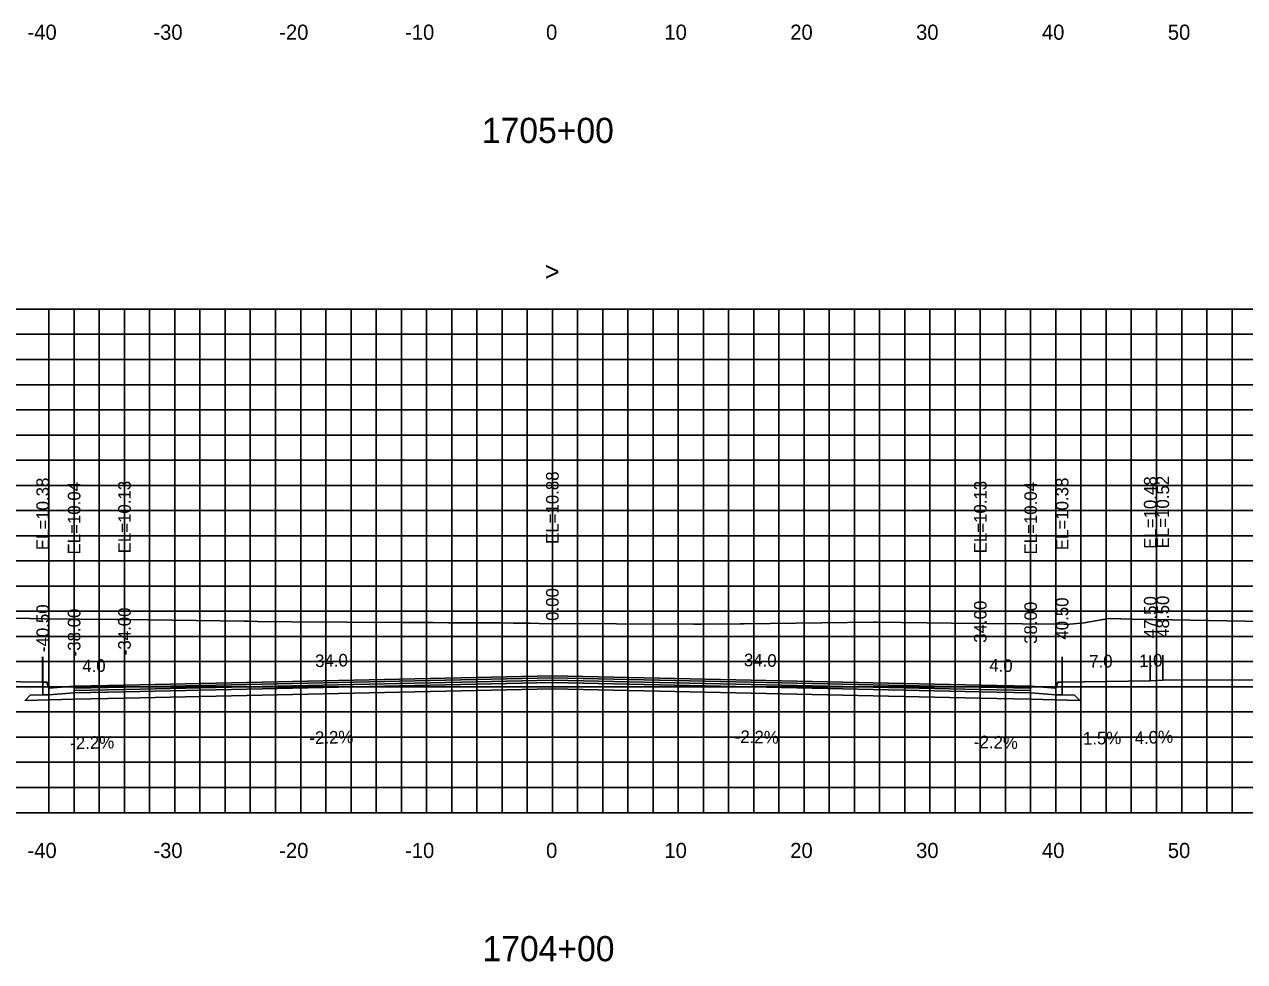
# Model space of a CAD drawing. Extents: x 1797789 to 1803805, y 249066 to 250293.
# Drawn here: x 1802929.1 to 1803026, y 250087.6 to 250162 of the extents above; entities that cross this region are included whole.
import ezdxf

# ---------------------------------------------------------------- set-up
doc = ezdxf.new("R2010")
doc.units = 0
for name, color, linetype in [('1', 7, 'Continuous'), ('10', 7, 'Continuous'), ('3', 7, 'Continuous'), ('4', 7, 'Continuous'), ('60', 7, 'Continuous'), ('BASE', 7, 'Continuous'), ('CL-CNST', 7, 'Continuous'), ('Level 62', 7, 'Continuous'), ('LOWER BINDER', 7, 'Continuous'), ('M-ROADS', 7, 'Continuous'), ('UPPER BINDER', 7, 'Continuous'), ('WEARING', 7, 'Continuous')]:
    doc.layers.add(name, color=color, linetype=linetype)

msp = doc.modelspace()

# ---------------------------------------------------------------- linework, layer by layer
for p, q in [((1802971.002, 250110.307), (1802971.002, 250112.307)), ((1802930.502, 250109.811), (1802930.502, 250111.811)), ((1802930.505, 250109.811), (1802930.505, 250111.811)), ((1802933.002, 250109.471), (1802933.002, 250111.471)), ((1802937.002, 250109.559), (1802937.002, 250111.559)), ((1803005.002, 250109.559), (1803005.002, 250111.559)), ((1803009.002, 250109.471), (1803009.002, 250111.471)), ((1803011.498, 250109.811), (1803011.498, 250111.811)), ((1803011.502, 250109.811), (1803011.502, 250111.811)), ((1803018.502, 250109.916), (1803018.502, 250111.916)), ((1803019.502, 250109.956), (1803019.502, 250111.956))]:
    msp.add_line(p, q)
for points in [[(1802933.002, 250109.471), (1802931.002, 250109.311), (1802930.835, 250109.811), (1802930.505, 250109.811), (1802930.505, 250108.781), (1802931.002, 250108.781), (1802933.002, 250108.941)], [(1803009.002, 250109.471), (1803011.002, 250109.311), (1803011.168, 250109.811), (1803011.498, 250109.811), (1803011.498, 250108.781), (1803011.002, 250108.781), (1803009.002, 250108.941)]]:
    msp.add_lwpolyline(points, close=True)
at = {"layer": '60'}
for p, q in [((1802821.002, 250099.432), (1803121.002, 250099.432)), ((1802931.002, 250099.372), (1802931.002, 250099.432)), ((1802941.002, 250099.372), (1802941.002, 250099.432)), ((1802951.002, 250099.372), (1802951.002, 250099.432)), ((1802961.002, 250099.372), (1802961.002, 250099.432)), ((1802971.002, 250099.372), (1802971.002, 250099.432)), ((1802981.002, 250099.372), (1802981.002, 250099.432)), ((1802991.002, 250099.372), (1802991.002, 250099.432)), ((1803001.002, 250099.372), (1803001.002, 250099.432)), ((1803011.002, 250099.372), (1803011.002, 250099.432)), ((1803021.002, 250099.372), (1803021.002, 250099.432))]:
    msp.add_line(p, q, dxfattribs=at)
at = {"layer": 'BASE'}
msp.add_lwpolyline([(1803009.002, 250108.441), (1803012.902, 250108.355), (1803012.498, 250108.759), (1803011.498, 250108.781), (1803011.002, 250108.781), (1803009.002, 250108.941), (1803005.002, 250109.029), (1802971.002, 250109.777), (1802937.002, 250109.029), (1802933.002, 250108.941), (1802931.002, 250108.781), (1802930.505, 250108.781), (1802929.505, 250108.759), (1802929.101, 250108.355), (1802933.002, 250108.441), (1802937.002, 250108.529), (1802971.002, 250109.277), (1803005.002, 250108.529)], close=True, dxfattribs=at)
at = {"layer": 'CL-CNST'}
msp.add_lwpolyline([(1802821.002, 250113.383), (1802922.502, 250109.956), (1802923.502, 250109.916), (1802930.502, 250109.811), (1802930.505, 250109.811), (1802930.835, 250109.811), (1802931.002, 250109.311), (1802933.002, 250109.471), (1802937.002, 250109.559), (1802971.002, 250110.307), (1803005.002, 250109.559), (1803009.002, 250109.471), (1803011.002, 250109.311), (1803011.168, 250109.811), (1803011.498, 250109.811), (1803011.502, 250109.811), (1803018.502, 250109.916), (1803019.502, 250109.956), (1803121.002, 250110.247)], dxfattribs=at)
at = {"layer": 'Level 62'}
for p, q in [((1802821.002, 250139.432), (1803121.002, 250139.432)), ((1802931.002, 250099.432), (1802931.002, 250139.432)), ((1802933.002, 250099.432), (1802933.002, 250139.432)), ((1802935.002, 250099.432), (1802935.002, 250139.432)), ((1802937.002, 250099.432), (1802937.002, 250139.432)), ((1802939.002, 250099.432), (1802939.002, 250139.432)), ((1802941.002, 250099.432), (1802941.002, 250139.432)), ((1802943.002, 250099.432), (1802943.002, 250139.432)), ((1802945.002, 250099.432), (1802945.002, 250139.432)), ((1802947.002, 250099.432), (1802947.002, 250139.432)), ((1802949.002, 250099.432), (1802949.002, 250139.432)), ((1802951.002, 250099.432), (1802951.002, 250139.432)), ((1802953.002, 250099.432), (1802953.002, 250139.432)), ((1802955.002, 250099.432), (1802955.002, 250139.432)), ((1802957.002, 250099.432), (1802957.002, 250139.432)), ((1802959.002, 250099.432), (1802959.002, 250139.432)), ((1802961.002, 250099.432), (1802961.002, 250139.432)), ((1802963.002, 250099.432), (1802963.002, 250139.432)), ((1802965.002, 250099.432), (1802965.002, 250139.432)), ((1802967.002, 250099.432), (1802967.002, 250139.432)), ((1802969.002, 250099.432), (1802969.002, 250139.432)), ((1802971.002, 250099.432), (1802971.002, 250139.432)), ((1802973.002, 250099.432), (1802973.002, 250139.432)), ((1802975.002, 250099.432), (1802975.002, 250139.432)), ((1802977.002, 250099.432), (1802977.002, 250139.432)), ((1802979.002, 250099.432), (1802979.002, 250139.432)), ((1802981.002, 250099.432), (1802981.002, 250139.432)), ((1802983.002, 250099.432), (1802983.002, 250139.432)), ((1802985.002, 250099.432), (1802985.002, 250139.432)), ((1802987.002, 250099.432), (1802987.002, 250139.432)), ((1802989.002, 250099.432), (1802989.002, 250139.432)), ((1802991.002, 250099.432), (1802991.002, 250139.432)), ((1802993.002, 250099.432), (1802993.002, 250139.432)), ((1802995.002, 250099.432), (1802995.002, 250139.432)), ((1802997.002, 250099.432), (1802997.002, 250139.432)), ((1802999.002, 250099.432), (1802999.002, 250139.432)), ((1803001.002, 250099.432), (1803001.002, 250139.432)), ((1803003.002, 250099.432), (1803003.002, 250139.432)), ((1803005.002, 250099.432), (1803005.002, 250139.432)), ((1803007.002, 250099.432), (1803007.002, 250139.432)), ((1803009.002, 250099.432), (1803009.002, 250139.432)), ((1803011.002, 250099.432), (1803011.002, 250139.432)), ((1803013.002, 250099.432), (1803013.002, 250139.432)), ((1803015.002, 250099.432), (1803015.002, 250139.432)), ((1803017.002, 250099.432), (1803017.002, 250139.432)), ((1803019.002, 250099.432), (1803019.002, 250139.432)), ((1803021.002, 250099.432), (1803021.002, 250139.432)), ((1803023.002, 250099.432), (1803023.002, 250139.432)), ((1803025.002, 250099.432), (1803025.002, 250139.432)), ((1802821.002, 250137.432), (1803121.002, 250137.432)), ((1802821.002, 250135.432), (1803121.002, 250135.432)), ((1802821.002, 250133.432), (1803121.002, 250133.432)), ((1802821.002, 250131.432), (1803121.002, 250131.432)), ((1802821.002, 250129.432), (1803121.002, 250129.432)), ((1802821.002, 250127.432), (1803121.002, 250127.432)), ((1802821.002, 250125.432), (1803121.002, 250125.432)), ((1802821.002, 250123.432), (1803121.002, 250123.432)), ((1802821.002, 250121.432), (1803121.002, 250121.432)), ((1802821.002, 250119.432), (1803121.002, 250119.432)), ((1802821.002, 250117.432), (1803121.002, 250117.432)), ((1802821.002, 250115.432), (1803121.002, 250115.432)), ((1802821.002, 250113.432), (1803121.002, 250113.432)), ((1802821.002, 250111.432), (1803121.002, 250111.432)), ((1802821.002, 250109.432), (1803121.002, 250109.432)), ((1802821.002, 250107.432), (1803121.002, 250107.432)), ((1802821.002, 250105.432), (1803121.002, 250105.432)), ((1802821.002, 250103.432), (1803121.002, 250103.432)), ((1802821.002, 250101.432), (1803121.002, 250101.432)), ((1802821.002, 250099.432), (1803121.002, 250099.432))]:
    msp.add_line(p, q, dxfattribs=at)
at = {"layer": 'LOWER BINDER'}
msp.add_lwpolyline([(1802933.002, 250108.941), (1802933.002, 250109.131), (1802937.002, 250109.219), (1802971.002, 250109.967), (1803005.002, 250109.219), (1803009.002, 250109.131), (1803009.002, 250108.941), (1803005.002, 250109.029), (1802971.002, 250109.777), (1802937.002, 250109.029)], close=True, dxfattribs=at)
at = {"layer": 'M-ROADS'}
msp.add_lwpolyline([(1802921.527, 250115.038), (1802930.633, 250114.837), (1802936.36, 250114.784), (1802936.602, 250114.783), (1802936.979, 250114.781), (1802946.509, 250114.642), (1802946.863, 250114.639), (1802947.563, 250114.632), (1802950.301, 250114.599), (1802959.049, 250114.542), (1802959.905, 250114.538), (1802960.894, 250114.531), (1802961.539, 250114.527), (1802962.737, 250114.521), (1802967.073, 250114.504), (1802967.925, 250114.494), (1802969.103, 250114.475), (1802969.221, 250114.474), (1802969.961, 250114.468), (1802982.232, 250114.405), (1802982.605, 250114.407), (1802982.817, 250114.407), (1802985.931, 250114.439), (1802986.232, 250114.439), (1802996.527, 250114.562), (1802996.758, 250114.563), (1803002.713, 250114.485), (1803011.131, 250114.398), (1803011.472, 250114.426), (1803011.825, 250114.383), (1803013.244, 250114.514), (1803015.203, 250114.853), (1803018.085, 250114.782), (1803018.298, 250114.779), (1803018.774, 250114.771), (1803027.499, 250114.63)], dxfattribs=at)
at = {"layer": 'UPPER BINDER'}
msp.add_lwpolyline([(1802971.002, 250109.967), (1802937.002, 250109.219), (1802933.002, 250109.131), (1802933.002, 250109.321), (1802937.002, 250109.409), (1802971.002, 250110.157), (1803005.002, 250109.409), (1803009.002, 250109.321), (1803009.002, 250108.941), (1803009.002, 250109.131), (1803005.002, 250109.219)], close=True, dxfattribs=at)
at = {"layer": 'WEARING'}
msp.add_lwpolyline([(1803009.002, 250109.321), (1803009.002, 250109.471), (1803005.002, 250109.559), (1802971.002, 250110.307), (1802937.002, 250109.559), (1802933.002, 250109.471), (1802933.002, 250109.321), (1802937.002, 250109.409), (1802971.002, 250110.157), (1803005.002, 250109.409)], close=True, dxfattribs=at)

# ---------------------------------------------------------------- texts
at = {"layer": '1'}
for s, p in [('1705+00', (1802965.402, 250152.632)), ('1704+00', (1802965.452, 250087.632))]:
    msp.add_text(s, height=2, dxfattribs=at).set_placement(p)
at = {"layer": '10'}
for s, p in [('-40', (1802929.298, 250160.832)), ('-30', (1802939.298, 250160.832)), ('-20', (1802949.298, 250160.832)), ('-10', (1802959.298, 250160.832)), ('0', (1802970.501, 250160.832)), ('10', (1802979.901, 250160.832)), ('20', (1802989.901, 250160.832)), ('30', (1802999.901, 250160.832)), ('40', (1803009.901, 250160.832)), ('50', (1803019.901, 250160.832)), ('-40', (1802929.298, 250095.832)), ('-30', (1802939.298, 250095.832)), ('-20', (1802949.298, 250095.832)), ('-10', (1802959.298, 250095.832)), ('0', (1802970.501, 250095.832)), ('10', (1802979.901, 250095.832)), ('20', (1802989.901, 250095.832)), ('30', (1802999.901, 250095.832)), ('40', (1803009.901, 250095.832)), ('50', (1803019.901, 250095.832))]:
    msp.add_text(s, height=1.2, dxfattribs=at).set_placement(p)
at = {"layer": '3'}
for s, p in [('EL=10.38', (1802931.002, 250120.284)), ('EL=10.38', (1802931.005, 250120.283)), ('EL=10.88', (1802971.502, 250120.779)), ('EL=10.38', (1803011.998, 250120.283)), ('EL=10.38', (1803012.002, 250120.284)), ('EL=10.48', (1803019.002, 250120.389)), ('EL=10.52', (1803020.002, 250120.429)), ('EL=10.04', (1802933.502, 250119.943)), ('EL=10.13', (1802937.502, 250120.031)), ('EL=10.13', (1803005.502, 250120.031)), ('EL=10.04', (1803009.502, 250119.943)), ('0.00', (1802971.502, 250114.669)), ('34.00', (1803005.502, 250112.929)), ('38.00', (1803009.502, 250112.841)), ('40.50', (1803011.998, 250113.181)), ('40.50', (1803012.002, 250113.181)), ('47.50', (1803019.002, 250113.286)), ('48.50', (1803020.002, 250113.326)), ('-40.50', (1802931.002, 250112.189)), ('-40.50', (1802931.005, 250112.189)), ('-38.00', (1802933.502, 250111.849)), ('-34.00', (1802937.502, 250111.937))]:
    msp.add_text(s, height=1, rotation=90, dxfattribs=at).set_placement(p)
at = {"layer": '4'}
for s, rotation, p in [('4.0', 1.2603, (1802933.655, 250110.586)), ('34.0', 1.2603, (1802952.159, 250110.993)), ('34.0', 358.7397, (1802986.207, 250111.073)), ('4.0', 358.7397, (1803005.703, 250110.644)), ('7.0', 0.85937, (1803013.662, 250110.944)), ('1.0', 2.29061, (1803017.636, 250110.982)), ('-2.2%', 1.2603, (1802932.703, 250104.463)), ('-2.2%', 1.2603, (1802951.703, 250104.881)), ('-2.2%', 358.7397, (1802985.483, 250104.987)), ('-2.2%', 358.7397, (1803004.483, 250104.569)), ('1.5%', 0.85937, (1803013.163, 250104.835)), ('4.0%', 2.29061, (1803017.29, 250104.864))]:
    msp.add_text(s, height=1, rotation=rotation, dxfattribs=at).set_placement(p)
at = {"layer": '60'}
msp.add_text('>', height=1.5, dxfattribs=at).set_placement((1802970.393, 250141.682))

doc.saveas('drawing.dxf')
